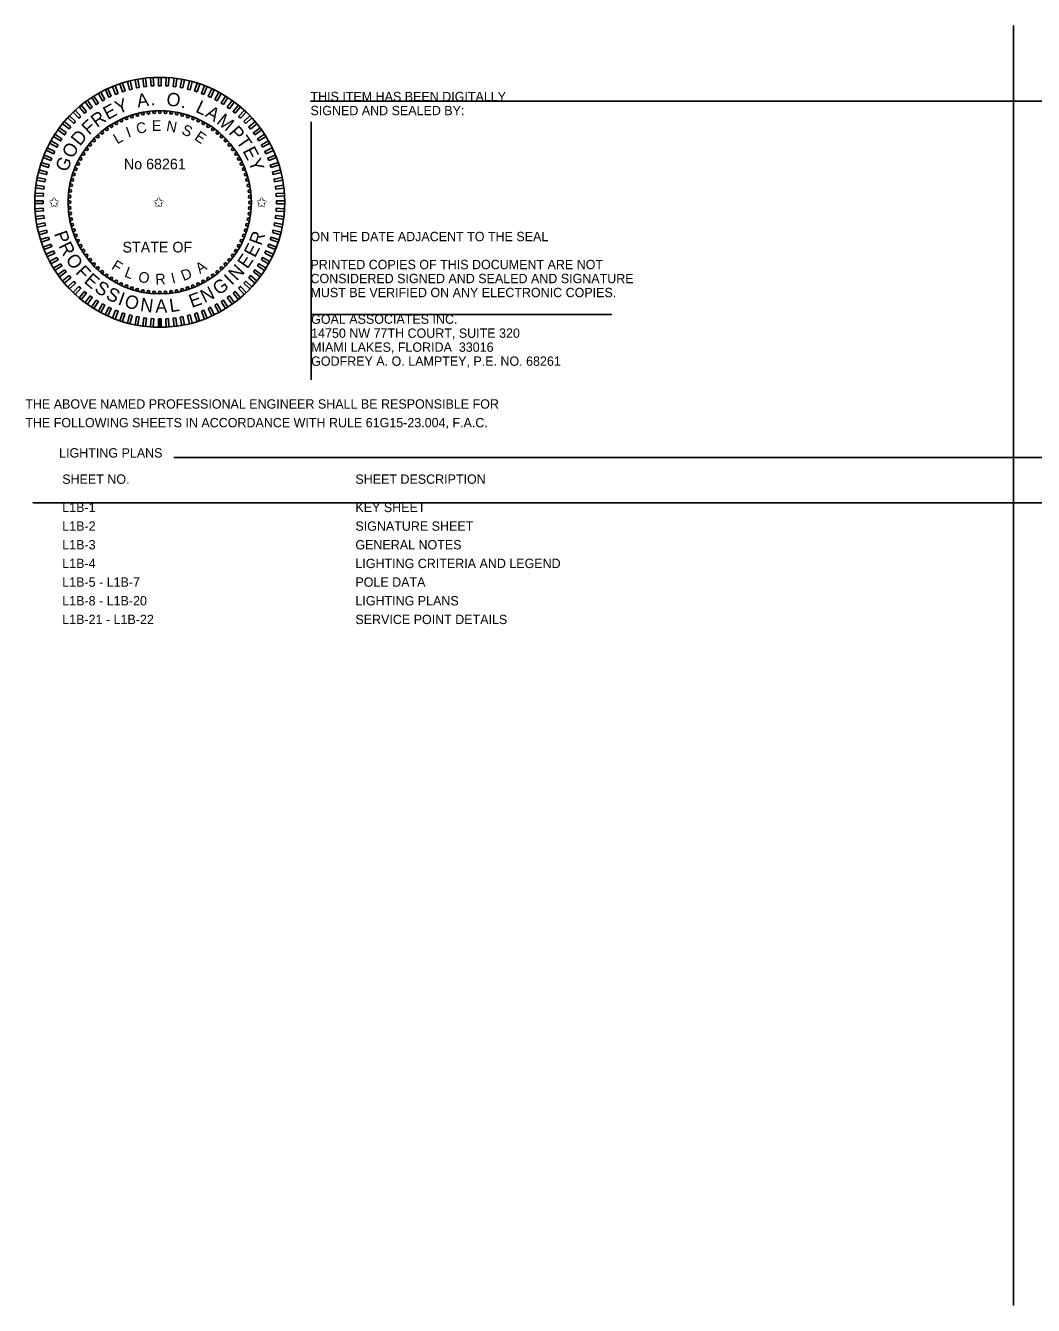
# Model space of a CAD drawing. Extents: x -811.2 to -755.6, y -2295.2 to -2235.1.
# Drawn here: x -810.5 to -802.94, y -2244.66 to -2235.06 of the extents above; entities that cross this region are included whole.
import ezdxf

# ---------------------------------------------------------------- set-up
doc = ezdxf.new("R2010")
doc.units = 0
for name, color, linetype in [('Logo_dp', 7, 'Continuous'), ('NonPlottingEle_dp', 7, 'Continuous'), ('ScratchEle_dp', 7, 'Continuous'), ('SheetBorder_dp', 7, 'Continuous'), ('TextMisc', 7, 'Continuous'), ('TextNotes', 7, 'Continuous')]:
    doc.layers.add(name, color=color, linetype=linetype)

msp = doc.modelspace()

# ---------------------------------------------------------------- linework, layer by layer
at = {"layer": 'Logo_dp'}
for p, q in [((-809.5001, -2237.3253), (-809.5003, -2237.2628)), ((-809.4901, -2237.3252), (-809.4903, -2237.2627)), ((-809.4801, -2237.3252), (-809.4803, -2237.2627))]:
    msp.add_line(p, q, dxfattribs=at)
for points in [[(-809.5349, -2235.5138), (-809.555, -2235.5151), (-809.559, -2235.4527), (-809.5388, -2235.4515)], [(-809.4799, -2235.5127), (-809.5001, -2235.5127), (-809.5001, -2235.4503), (-809.4799, -2235.4503)], [(-809.425, -2235.5151), (-809.4452, -2235.5138), (-809.4412, -2235.4515), (-809.4211, -2235.4528)], [(-809.8535, -2235.5917), (-809.8717, -2235.6002), (-809.8983, -2235.5438), (-809.8801, -2235.5352)], [(-809.8028, -2235.5704), (-809.8215, -2235.5778), (-809.8445, -2235.5198), (-809.8258, -2235.5124)], [(-809.7508, -2235.5524), (-809.77, -2235.5586), (-809.7893, -2235.4992), (-809.7701, -2235.493)], [(-809.6979, -2235.5377), (-809.7174, -2235.5427), (-809.7329, -2235.4822), (-809.7134, -2235.4772)], [(-809.6441, -2235.5263), (-809.6639, -2235.5301), (-809.6756, -2235.4688), (-809.6558, -2235.465)], [(-809.5897, -2235.5183), (-809.6097, -2235.5209), (-809.6175, -2235.4589), (-809.5975, -2235.4564)], [(-809.3703, -2235.5209), (-809.3904, -2235.5184), (-809.3825, -2235.4564), (-809.3625, -2235.4589)], [(-809.3162, -2235.5301), (-809.336, -2235.5263), (-809.3243, -2235.465), (-809.3045, -2235.4688)], [(-809.2626, -2235.5427), (-809.2822, -2235.5377), (-809.2667, -2235.4772), (-809.2471, -2235.4823)], [(-809.21, -2235.5587), (-809.2292, -2235.5524), (-809.2099, -2235.4931), (-809.1907, -2235.4993)], [(-809.1585, -2235.5779), (-809.1773, -2235.5705), (-809.1543, -2235.5124), (-809.1355, -2235.5199)], [(-809.1083, -2235.6003), (-809.1266, -2235.5917), (-809.1, -2235.5352), (-809.0817, -2235.5438)], [(-809.9962, -2235.6738), (-810.0125, -2235.6857), (-810.0492, -2235.6352), (-810.0329, -2235.6233)], [(-809.9504, -2235.6435), (-809.9674, -2235.6543), (-810.0009, -2235.6016), (-809.9838, -2235.5908)], [(-809.9027, -2235.616), (-809.9204, -2235.6258), (-809.9505, -2235.571), (-809.9328, -2235.5613)], [(-809.0596, -2235.6259), (-809.0773, -2235.6161), (-809.0473, -2235.5614), (-809.0296, -2235.5711)], [(-809.0127, -2235.6544), (-809.0297, -2235.6436), (-808.9962, -2235.5909), (-808.9792, -2235.6017)], [(-808.9676, -2235.6858), (-808.9839, -2235.674), (-808.9472, -2235.6234), (-808.9308, -2235.6353)], [(-810.121, -2235.7813), (-810.1348, -2235.796), (-810.1804, -2235.7533), (-810.1665, -2235.7386)], [(-810.0817, -2235.7429), (-810.0964, -2235.7567), (-810.1392, -2235.7112), (-810.1244, -2235.6974)], [(-810.04, -2235.707), (-810.0556, -2235.7199), (-810.0954, -2235.6718), (-810.0798, -2235.6589)], [(-808.9245, -2235.72), (-808.9401, -2235.7071), (-808.9003, -2235.659), (-808.8847, -2235.6719)], [(-808.8837, -2235.7568), (-808.8984, -2235.743), (-808.8557, -2235.6975), (-808.841, -2235.7113)], [(-808.8453, -2235.7962), (-808.8591, -2235.7815), (-808.8136, -2235.7387), (-808.7998, -2235.7534)], [(-810.192, -2235.8652), (-810.2039, -2235.8815), (-810.2544, -2235.8448), (-810.2426, -2235.8285)], [(-810.1579, -2235.8221), (-810.1707, -2235.8377), (-810.2188, -2235.7979), (-810.206, -2235.7823)], [(-808.8094, -2235.8378), (-808.8223, -2235.8223), (-808.7742, -2235.7825), (-808.7613, -2235.798)], [(-808.7762, -2235.8817), (-808.7881, -2235.8653), (-808.7376, -2235.8286), (-808.7257, -2235.845)], [(-810.252, -2235.9573), (-810.2617, -2235.975), (-810.3164, -2235.9449), (-810.3067, -2235.9272)], [(-810.2235, -2235.9103), (-810.2343, -2235.9273), (-810.287, -2235.8939), (-810.2762, -2235.8768)], [(-808.7459, -2235.9275), (-808.7567, -2235.9104), (-808.7039, -2235.877), (-808.6931, -2235.894)], [(-808.7184, -2235.9751), (-808.7281, -2235.9574), (-808.6734, -2235.9273), (-808.6637, -2235.945)], [(-810.2775, -2236.006), (-810.2861, -2236.0242), (-810.3426, -2235.9976), (-810.334, -2235.9794)], [(-808.694, -2236.0244), (-808.7026, -2236.0061), (-808.6461, -2235.9795), (-808.6375, -2235.9978)], [(-810.3192, -2236.1077), (-810.3254, -2236.1269), (-810.3848, -2236.1076), (-810.3786, -2236.0884)], [(-810.3, -2236.0562), (-810.3074, -2236.0749), (-810.3654, -2236.0519), (-810.358, -2236.0332)], [(-808.6728, -2236.0751), (-808.6802, -2236.0563), (-808.6222, -2236.0333), (-808.6147, -2236.0521)], [(-808.6548, -2236.127), (-808.661, -2236.1078), (-808.6016, -2236.0885), (-808.5954, -2236.1077)], [(-810.3477, -2236.2138), (-810.3515, -2236.2336), (-810.4129, -2236.2219), (-810.4091, -2236.2021)], [(-810.3351, -2236.1603), (-810.3401, -2236.1798), (-810.4006, -2236.1643), (-810.3956, -2236.1447)], [(-808.64, -2236.18), (-808.6451, -2236.1604), (-808.5846, -2236.1449), (-808.5796, -2236.1645)], [(-808.6287, -2236.2338), (-808.6325, -2236.214), (-808.5711, -2236.2023), (-808.5673, -2236.2221)], [(-810.3628, -2236.3226), (-810.3641, -2236.3428), (-810.4264, -2236.3389), (-810.4251, -2236.3187)], [(-810.357, -2236.268), (-810.3595, -2236.288), (-810.4215, -2236.2802), (-810.4189, -2236.2601)], [(-808.6207, -2236.2882), (-808.6232, -2236.2682), (-808.5613, -2236.2603), (-808.5588, -2236.2804)], [(-808.6162, -2236.343), (-808.6174, -2236.3228), (-808.5551, -2236.3189), (-808.5539, -2236.339)], [(-810.3652, -2236.3776), (-810.3652, -2236.3977), (-810.4276, -2236.3977), (-810.4276, -2236.3776)], [(-808.6151, -2236.3979), (-808.6151, -2236.3777), (-808.5527, -2236.3777), (-808.5527, -2236.3979)], [(-810.3641, -2236.4325), (-810.3628, -2236.4527), (-810.4251, -2236.4566), (-810.4264, -2236.4364)], [(-810.3595, -2236.4873), (-810.357, -2236.5073), (-810.4189, -2236.5152), (-810.4215, -2236.4951)], [(-808.6233, -2236.5075), (-808.6207, -2236.4875), (-808.5588, -2236.4953), (-808.5613, -2236.5153)], [(-808.6175, -2236.4529), (-808.6162, -2236.4327), (-808.5539, -2236.4366), (-808.5551, -2236.4568)], [(-810.3516, -2236.5417), (-810.3478, -2236.5615), (-810.4091, -2236.5732), (-810.4129, -2236.5534)], [(-810.3402, -2236.5955), (-810.3352, -2236.615), (-810.3957, -2236.6306), (-810.4007, -2236.611)], [(-808.6451, -2236.6152), (-808.6401, -2236.5957), (-808.5796, -2236.6112), (-808.5846, -2236.6307)], [(-808.6325, -2236.5617), (-808.6287, -2236.5419), (-808.5674, -2236.5536), (-808.5712, -2236.5734)], [(-810.3255, -2236.6485), (-810.3192, -2236.6677), (-810.3786, -2236.6869), (-810.3849, -2236.6677)], [(-810.3075, -2236.7004), (-810.3, -2236.7192), (-810.3581, -2236.7421), (-810.3655, -2236.7234)], [(-808.6803, -2236.7193), (-808.6729, -2236.7006), (-808.6148, -2236.7236), (-808.6222, -2236.7423)], [(-808.6611, -2236.6678), (-808.6548, -2236.6486), (-808.5954, -2236.6679), (-808.6017, -2236.6871)], [(-810.2862, -2236.7511), (-810.2776, -2236.7694), (-810.3341, -2236.7959), (-810.3427, -2236.7777)], [(-808.7027, -2236.7695), (-808.6941, -2236.7513), (-808.6376, -2236.7778), (-808.6462, -2236.7961)], [(-810.2618, -2236.8004), (-810.2521, -2236.8181), (-810.3068, -2236.8481), (-810.3165, -2236.8304)], [(-810.2344, -2236.848), (-810.2236, -2236.8651), (-810.2763, -2236.8985), (-810.2871, -2236.8815)], [(-810.204, -2236.8938), (-810.1922, -2236.9102), (-810.2427, -2236.9469), (-810.2545, -2236.9305)], [(-808.7882, -2236.9103), (-808.7763, -2236.894), (-808.7258, -2236.9307), (-808.7377, -2236.947)], [(-808.7568, -2236.8652), (-808.746, -2236.8482), (-808.6932, -2236.8816), (-808.704, -2236.8987)], [(-808.7282, -2236.8182), (-808.7185, -2236.8005), (-808.6638, -2236.8306), (-808.6735, -2236.8483)], [(-810.1708, -2236.9377), (-810.158, -2236.9532), (-810.2061, -2236.993), (-810.2189, -2236.9775)], [(-810.135, -2236.9793), (-810.1211, -2236.994), (-810.1667, -2237.0368), (-810.1805, -2237.0221)], [(-808.8592, -2236.9942), (-808.8454, -2236.9795), (-808.7999, -2237.0222), (-808.8137, -2237.0369)], [(-808.8224, -2236.9534), (-808.8095, -2236.9378), (-808.7614, -2236.9776), (-808.7743, -2236.9932)], [(-810.0965, -2237.0186), (-810.0818, -2237.0325), (-810.1246, -2237.078), (-810.1393, -2237.0642)], [(-810.0557, -2237.0555), (-810.0402, -2237.0683), (-810.08, -2237.1164), (-810.0955, -2237.1036)], [(-808.9402, -2237.0685), (-808.9247, -2237.0556), (-808.8848, -2237.1037), (-808.9004, -2237.1166)], [(-808.8985, -2237.0326), (-808.8838, -2237.0188), (-808.8411, -2237.0643), (-808.8558, -2237.0781)], [(-810.0127, -2237.0897), (-809.9964, -2237.1015), (-810.0331, -2237.152), (-810.0494, -2237.1402)], [(-809.9676, -2237.1211), (-809.9505, -2237.1319), (-809.984, -2237.1846), (-810.001, -2237.1738)], [(-809.9206, -2237.1496), (-809.9029, -2237.1594), (-809.933, -2237.2141), (-809.9507, -2237.2043)], [(-809.8719, -2237.1752), (-809.8536, -2237.1838), (-809.8802, -2237.2402), (-809.8985, -2237.2317)], [(-809.1268, -2237.1838), (-809.1085, -2237.1752), (-809.0819, -2237.2317), (-809.1002, -2237.2403)], [(-809.0775, -2237.1594), (-809.0598, -2237.1497), (-809.0297, -2237.2044), (-809.0474, -2237.2142)], [(-809.0299, -2237.132), (-809.0128, -2237.1212), (-808.9794, -2237.1739), (-808.9964, -2237.1847)], [(-808.984, -2237.1016), (-808.9677, -2237.0898), (-808.931, -2237.1403), (-808.9473, -2237.1522)], [(-809.8217, -2237.1976), (-809.8029, -2237.205), (-809.8259, -2237.2631), (-809.8447, -2237.2556)], [(-809.7702, -2237.2168), (-809.751, -2237.223), (-809.7703, -2237.2824), (-809.7895, -2237.2762)], [(-809.7176, -2237.2327), (-809.698, -2237.2378), (-809.7136, -2237.2982), (-809.7331, -2237.2932)], [(-809.6641, -2237.2454), (-809.6443, -2237.2491), (-809.656, -2237.3105), (-809.6758, -2237.3067)], [(-809.6099, -2237.2546), (-809.5899, -2237.2571), (-809.5977, -2237.3191), (-809.6177, -2237.3165)], [(-809.5552, -2237.2604), (-809.5351, -2237.2617), (-809.539, -2237.324), (-809.5592, -2237.3227)], [(-809.5003, -2237.2628), (-809.4801, -2237.2628), (-809.4801, -2237.3252), (-809.5003, -2237.3252)], [(-809.4453, -2237.2617), (-809.4252, -2237.2604), (-809.4213, -2237.3227), (-809.4414, -2237.324)], [(-809.3906, -2237.2571), (-809.3705, -2237.2546), (-809.3627, -2237.3166), (-809.3827, -2237.3191)], [(-809.3362, -2237.2492), (-809.3163, -2237.2454), (-809.3046, -2237.3067), (-809.3245, -2237.3105)], [(-809.2824, -2237.2378), (-809.2628, -2237.2328), (-809.2473, -2237.2933), (-809.2668, -2237.2983)], [(-809.2294, -2237.2231), (-809.2102, -2237.2169), (-809.1909, -2237.2762), (-809.2101, -2237.2825)], [(-809.1775, -2237.2051), (-809.1587, -2237.1976), (-809.1357, -2237.2557), (-809.1545, -2237.2631)]]:
    msp.add_lwpolyline(points, close=True, dxfattribs=at)
for centre in [(-809.6989, -2235.7433), (-809.6581, -2235.7314), (-809.6165, -2235.7222), (-809.5745, -2235.7155), (-809.5321, -2235.7116), (-809.4896, -2235.7103), (-809.447, -2235.7116), (-809.4047, -2235.7157), (-809.3626, -2235.7224), (-809.3211, -2235.7317), (-809.2802, -2235.7436), (-809.8879, -2235.8393), (-809.8527, -2235.8154), (-809.816, -2235.7938), (-809.7781, -2235.7745), (-809.739, -2235.7576), (-809.2402, -2235.7581), (-809.2012, -2235.775), (-809.1633, -2235.7943), (-809.1266, -2235.816), (-809.0915, -2235.84), (-809.9836, -2235.9236), (-809.9535, -2235.8935), (-809.9215, -2235.8654), (-809.0579, -2235.8661), (-809.026, -2235.8943), (-808.9959, -2235.9244), (-810.0618, -2236.0243), (-810.0379, -2235.9891), (-810.0118, -2235.9555), (-808.9678, -2235.9563), (-808.9417, -2235.99), (-808.9178, -2236.0252), (-810.1198, -2236.1378), (-810.1029, -2236.0988), (-810.0835, -2236.0609), (-808.8962, -2236.0619), (-808.8769, -2236.0998), (-810.1462, -2236.2187), (-810.1343, -2236.1779), (-808.86, -2236.1389), (-808.8456, -2236.1789), (-808.8338, -2236.2198), (-810.1622, -2236.3023), (-810.1555, -2236.2602), (-808.8245, -2236.2614), (-808.8179, -2236.3034), (-810.1676, -2236.3872), (-810.1662, -2236.3446), (-808.814, -2236.3458), (-808.8127, -2236.3883), (-810.1663, -2236.4297), (-810.1623, -2236.4721), (-810.1557, -2236.5141), (-808.8248, -2236.5152), (-808.8181, -2236.4732), (-808.814, -2236.4308), (-810.1464, -2236.5557), (-810.1346, -2236.5966), (-808.846, -2236.5976), (-808.8341, -2236.5568), (-810.1202, -2236.6366), (-810.1034, -2236.6757), (-810.0841, -2236.7136), (-808.8774, -2236.6767), (-808.8604, -2236.6377), (-810.0624, -2236.7503), (-810.0385, -2236.7855), (-808.9424, -2236.7864), (-808.9184, -2236.7512), (-808.8967, -2236.7146), (-810.0125, -2236.8191), (-809.9844, -2236.8511), (-809.9543, -2236.8812), (-809.0268, -2236.882), (-808.9967, -2236.8519), (-808.9685, -2236.82), (-809.9224, -2236.9094), (-809.8888, -2236.9355), (-809.8536, -2236.9594), (-809.817, -2236.9811), (-809.7791, -2237.0005), (-809.2022, -2237.001), (-809.1642, -2236.9817), (-809.1276, -2236.96), (-809.0924, -2236.9362), (-809.0587, -2236.9101), (-809.74, -2237.0174), (-809.7, -2237.0319), (-809.6591, -2237.0438), (-809.6176, -2237.0531), (-809.5756, -2237.0598), (-809.5332, -2237.0638), (-809.4901, -2237.0652), (-809.4481, -2237.0639), (-809.4058, -2237.0599), (-809.3637, -2237.0533), (-809.3222, -2237.0441), (-809.2813, -2237.0322), (-809.2413, -2237.0178)]:
    msp.add_circle(centre, 0.01, dxfattribs=at)
at = {"layer": 'NonPlottingEle_dp'}
for radius in [0.9375, 0.6875]:
    msp.add_circle((-809.4901, -2236.3877), radius, dxfattribs=at)
at = {"layer": 'ScratchEle_dp'}
for p, q in [((-808.3596, -2235.6292), (-796.8708, -2235.6292)), ((-808.3546, -2235.7843), (-808.3546, -2237.719)), ((-808.3546, -2237.229), (-806.0979, -2237.229)), ((-809.3854, -2238.3022), (-800.7818, -2238.3022)), ((-801.9648, -2238.6414), (-810.4432, -2238.6414))]:
    msp.add_line(p, q, dxfattribs=at)
at = {"layer": 'SheetBorder_dp'}
msp.add_line((-803.0858, -2244.6621), (-803.0858, -2235.0621), dxfattribs=at)

# ---------------------------------------------------------------- texts
at = {"layer": 'Logo_dp'}
for s, height, rotation, p in [('E', 0.1, 28.10553, (-809.8806, -2235.7716)), ('Y', 0.1, 21.06329, (-809.8021, -2235.7283)), ('A', 0.1, 8.80884, (-809.6551, -2235.6771)), ('.', 0.1, 1.04184, (-809.5575, -2235.6613)), ('O', 0.1, 352.18771, (-809.4449, -2235.6596)), ('L', 0.1, 334.67271, (-809.2279, -2235.707)), ('R', 0.1, 35.92688, (-809.9609, -2235.8304)), ('.', 0.1, 343.52684, (-809.3358, -2235.6747)), ('A', 0.1, 328.40959, (-809.1552, -2235.7397)), ('M', 0.1, 320.6426, (-809.0707, -2235.7909)), ('F', 0.1, 42.37723, (-810.0205, -2235.8868)), ('I', 0.08, 20.01168, (-809.7258, -2235.9037)), ('C', 0.08, 12.20255, (-809.6579, -2235.8761)), ('E', 0.08, 0.41861, (-809.5498, -2235.8527)), ('N', 0.08, 349.29143, (-809.4455, -2235.8512)), ('S', 0.08, 337.02207, (-809.3325, -2235.8729)), ('P', 0.1, 311.19658, (-808.9784, -2235.8678)), ('D', 0.1, 50.8569, (-810.0886, -2235.9705)), ('L', 0.08, 30.40215, (-809.8093, -2235.9541)), ('E', 0.08, 325.86633, (-809.2358, -2235.9132)), ('T', 0.1, 304.45632, (-808.9209, -2235.9315)), ('O', 0.1, 59.51777, (-810.1446, -2236.0654)), ('E', 0.1, 297.63152, (-808.8707, -2236.0023)), ('G', 0.1, 68.0518, (-810.1851, -2236.1661)), ('Y', 0.1, 290.58928, (-808.8281, -2236.0812)), ('P', 0.1, 289.40551, (-810.2848, -2236.6223)), ('R', 0.1, 69.5134, (-808.7299, -2236.7174)), ('R', 0.1, 296.14576, (-810.2518, -2236.714)), ('E', 0.1, 62.47116, (-808.7761, -2236.8082)), ('O', 0.1, 303.96711, (-810.2003, -2236.8146)), ('E', 0.1, 55.42892, (-808.833, -2236.8925)), ('F', 0.1, 312.62798, (-810.1279, -2236.9167)), ('F', 0.08, 328.72408, (-809.8582, -2236.8843)), ('L', 0.08, 339.29159, (-809.7609, -2236.9434)), ('D', 0.08, 22.01279, (-809.312, -2236.9796)), ('A', 0.08, 34.49917, (-809.1883, -2236.9271)), ('N', 0.1, 47.17876, (-808.9123, -2236.9816)), ('E', 0.1, 319.07833, (-810.0645, -2236.985)), ('S', 0.1, 326.12056, (-809.9869, -2237.0509)), ('O', 0.08, 349.68206, (-809.6562, -2236.9831)), ('R', 0.08, 2.33977, (-809.5217, -2237.005)), ('I', 0.08, 14.20366, (-809.3941, -2236.9984)), ('G', 0.1, 35.11153, (-809.0492, -2237.0893)), ('I', 0.1, 43.64556, (-808.9499, -2237.0161)), ('S', 0.1, 333.193, (-809.9015, -2237.107)), ('I', 0.1, 340.26543, (-809.8098, -2237.1522)), ('O', 0.1, 343.79863, (-809.7621, -2237.1704)), ('E', 0.1, 19.81912, (-809.2498, -2237.1807)), ('N', 0.1, 26.86136, (-809.1544, -2237.1453)), ('N', 0.1, 352.45949, (-809.6411, -2237.2025)), ('A', 0.1, 0.70966, (-809.5227, -2237.2157)), ('L', 0.1, 8.47665, (-809.4105, -2237.2125))]:
    msp.add_text(s, height=height, rotation=rotation, dxfattribs=at).set_placement(p)
for s, p in [('No 68261', (-809.7591, -2236.1405)), ('✩', (-810.3251, -2236.4257)), ('✩', (-809.5404, -2236.4257)), ('✩', (-808.7685, -2236.4257)), ('STATE OF', (-809.7698, -2236.7639))]:
    msp.add_text(s, height=0.08, dxfattribs=at).set_placement(p)
at = {"layer": 'TextMisc'}
for s, p in [('THIS ITEM HAS BEEN DIGITALLY', (-808.3596, -2235.6292)), ('SIGNED AND SEALED BY:', (-808.3596, -2235.7342)), ('ON THE DATE ADJACENT TO THE SEAL', (-808.3596, -2236.6792)), ('PRINTED COPIES OF THIS DOCUMENT ARE NOT ', (-808.3596, -2236.8892)), ('CONSIDERED SIGNED AND SEALED AND SIGNATURE ', (-808.3596, -2236.9942)), ('MUST BE VERIFIED ON ANY ELECTRONIC COPIES.', (-808.3596, -2237.0992)), ('GOAL ASSOCIATES INC.', (-808.3546, -2237.299)), ('14750 NW 77TH COURT, SUITE 320', (-808.3546, -2237.404)), ('MIAMI LAKES, FLORIDA  33016', (-808.3546, -2237.509)), ('GODFREY A. O. LAMPTEY, P.E. NO. 68261', (-808.3546, -2237.614)), ('THE ABOVE NAMED PROFESSIONAL ENGINEER SHALL BE RESPONSIBLE FOR ', (-810.4987, -2237.9352)), ('THE FOLLOWING SHEETS IN ACCORDANCE WITH RULE 61G15-23.004, F.A.C.', (-810.4987, -2238.0752)), ('LIGHTING PLANS', (-810.245, -2238.3022))]:
    msp.add_text(s, height=0.07, dxfattribs=at).set_placement(p)
at = {"layer": 'TextNotes'}
for s, p in [('SHEET NO.', (-810.2215, -2238.4992)), ('SHEET DESCRIPTION', (-808.0226, -2238.4992)), ('L1B-1', (-810.2215, -2238.7114)), ('KEY SHEET', (-808.0226, -2238.7114)), ('L1B-2', (-810.2215, -2238.8514)), ('SIGNATURE SHEET', (-808.0226, -2238.8514)), ('L1B-3', (-810.2215, -2238.9914)), ('GENERAL NOTES', (-808.0226, -2238.9914)), ('L1B-4', (-810.2215, -2239.1314)), ('LIGHTING CRITERIA AND LEGEND', (-808.0226, -2239.1314)), ('L1B-5 - L1B-7', (-810.2215, -2239.2714)), ('POLE DATA', (-808.0226, -2239.2714)), ('L1B-8 - L1B-20', (-810.2215, -2239.4114)), ('LIGHTING PLANS', (-808.0226, -2239.4114)), ('L1B-21 - L1B-22', (-810.2215, -2239.5514)), ('SERVICE POINT DETAILS', (-808.0226, -2239.5514))]:
    msp.add_text(s, height=0.07, dxfattribs=at).set_placement(p)

doc.saveas('drawing.dxf')
